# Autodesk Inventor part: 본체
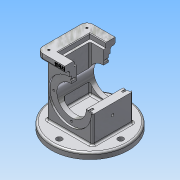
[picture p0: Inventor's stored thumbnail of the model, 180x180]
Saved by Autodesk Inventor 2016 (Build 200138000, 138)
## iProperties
Created: 2018-10
Part Number: 본체
Material: 알루미늄 6061
Document SubType Name: Modeling
Designer: Administrator
Density: 2.7 g/cm^3
Appearance: 알루미늄 - 평지
Mass: 984.575 g
Surface Area: 743.905 cm^2
Volume: 364.657 cm^3
Author: Administrator
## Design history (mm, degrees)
sketch "스케치1"
  geometry: C1 r 62.5 at (0, 0); 1 further point
  constraints: 1 centre point, 1 coincident
  dimensions: "d0" = 125 diameter of C1
extrude "돌출1" new body sketch "스케치1" distance "d1" = 10; taper "d2" = 0 deg
sketch "스케치3"
  geometry: L1 (-37, 33)-(37, 33); L2 (37, 33)-(37, -33); L3 (37, -33)-(-37, -33); L4 (-37, -33)-(-37, 33); L5 (-37, 33)-(37, -33); L6 (37, 33)-(-37, -33); 1 further point
  constraints: 12 end point, 2 midpoint, 2 parallel, 1 horizontal, 1 perpendicular
  dimensions: "d3" = 74 distance of L2.end L3.end; "d4" = 66 distance of L1.end L2.end
extrude "돌출2" join sketch "스케치3" distance "d5" = 108; taper "d6" = 0 deg
sketch "스케치4"
  geometry: L1 (-46, 41)-(46, 41); L2 (46, 41)-(46, -41); L3 (46, -41)-(-46, -41); L4 (-46, -41)-(-46, 41); L5 (-46, 41)-(46, -41); L6 (46, 41)-(-46, -41); 1 further point
  constraints: 12 end point, 2 midpoint, 2 parallel, 1 horizontal, 1 perpendicular
  dimensions: "d7" = 92 distance of L2.end L3.end; "d8" = 82 distance of L1.end L2.end
extrude "돌출3" join sketch "스케치4" distance "d9" = 10; taper "d10" = 0 deg
sketch "스케치5"
  geometry: L1 (0, 0)-(0, 18); L2 (0, 18)-(24.826, 18); L3 (24.826, 18)-(28, 0); L4 (28, 0)-(0, 0); 1 further point
  constraints: 8 end point, 1 coincident, 1 parallel, 1 perpendicular, 1 vertical
  dimensions: "d11" = 18 distance between parallel lines of L4 L2; "d12" = 56 diameter of L3.end L1; "d13" = 80 deg angle of L4 L3
revolve "회전1" sketch "스케치5" stored, may be unused: angle "d14" = 90 deg
sketch "스케치6"
  geometry: L1 (-26, 26)-(26, 26); L2 (26, 26)-(26, -26); L3 (26, -26)-(-26, -26); L4 (-26, -26)-(-26, 26); L5 (-26, 26)-(26, -26); L6 (26, 26)-(-26, -26); 1 further point
  constraints: 12 end point, 2 midpoint, 2 parallel, 1 horizontal, 1 perpendicular
  dimensions: "d15" = 52 distance of L2.end L3.end; "d16" = 52 distance of L1.end L2.end
extrude "돌출4" cut sketch "스케치6" distance "d17" = 8; taper "d18" = 0 deg
sketch "스케치7"
  geometry: L1 (-22, 22)-(22, 22); L2 (22, 22)-(22, -22); L3 (22, -22)-(-22, -22); L4 (-22, -22)-(-22, 22); L5 (-22, 22)-(22, -22); L6 (22, 22)-(-22, -22); 1 further point
  constraints: 12 end point, 2 midpoint, 2 parallel, 1 horizontal, 1 perpendicular
  dimensions: "d19" = 44 distance of L2.end L3.end; "d20" = 44 distance of L1.end L2.end
extrude "돌출5" cut sketch "스케치7" distance "d21" = 74; taper "d22" = 0 deg
sketch "스케치8"
  geometry: 1 further point
sketch "스케치9"
  geometry: C1 r 35 at (37, 44); 1 further point
  constraints: 1 centre point, 1 vertical alignment
  dimensions: "d23" = 70 diameter of C1; "d24" = 54 distance of point (37, -10) C1.centre
extrude "돌출6" cut sketch "스케치9" distance "d25" = 3; taper "d26" = 0 deg
sketch "스케치10" dims "d27" = 58
  geometry: C1 r 35 at (0, 0) reference; 3 further points
  constraints: 2 vertical alignment, 1 coincident, 2 other
hole "구멍1" sketch "스케치10" at (0, 29) diameter "d28" = 3.242; stored, may be unused: countersink angle "d32" = 90 deg, drill point angle "d34" = 118 deg; dims "d29" = 4, "d30" = 4, "d31" = 2, "d33" = 6
sketch "스케치11"
  geometry: C1 r 35 at (0, 0) reference; C2 r 24 at (0, 0); 1 further point
  constraints: 1 centre point, 1 coincident
  dimensions: "d38" = 48 diameter of C2
extrude "돌출7" cut sketch "스케치11" stored distance "d39" = 3; taper "d40" = 0 deg
fillet "모깎기1" dims "d41" = 10
hole "구멍2" diameter "d44" = 3.242; stored, may be unused: countersink angle "d48" = 90 deg, drill point angle "d50" = 118 deg; dims "d42" = 10, "d43" = 10, "d45" = 4, "d46" = 4, "d47" = 2, "d49" = 6
hole "구멍3" diameter "d53" = 3.242; stored, may be unused: countersink angle "d57" = 90 deg, drill point angle "d59" = 118 deg; dims "d51" = 10, "d52" = 10, "d54" = 4, "d55" = 4, "d56" = 2, "d58" = 6
hole "구멍4" diameter "d62" = 3.242; stored, may be unused: countersink angle "d66" = 90 deg, drill point angle "d68" = 118 deg; dims "d60" = 10, "d61" = 10, "d63" = 4, "d64" = 4, "d65" = 2, "d67" = 6
hole "구멍5" diameter "d71" = 3.242; stored, may be unused: countersink angle "d75" = 90 deg, drill point angle "d77" = 118 deg; dims "d69" = 10, "d70" = 10, "d72" = 4, "d73" = 4, "d74" = 2, "d76" = 6
sketch "스케치12"
  geometry: 3 further points
  constraints: 2 horizontal alignment
  dimensions: "d78" = 37 distance of point (10, 33) point (-27, 33); "d79" = 43 distance of point (-70, 33) point (-27, 33)
hole "구멍6" sketch "스케치12" at (-70, 33) diameter "d80" = 4.134; stored, may be unused: countersink angle "d84" = 90 deg, drill point angle "d86" = 118 deg; dims "d81" = 10, "d82" = 4, "d83" = 2, "d85" = 14.2
sketch "스케치13"
  geometry: 2 further points
  constraints: 1 horizontal alignment
  dimensions: "d87" = 37 distance of point (10, 33) point (-27, 33)
hole "구멍7" sketch "스케치13" at (-27, 33) diameter "d88" = 4.134; stored, may be unused: countersink angle "d92" = 90 deg, drill point angle "d94" = 118 deg; dims "d89" = 10, "d90" = 4, "d91" = 2, "d93" = 14.2
sketch "스케치15" dims "d95" = 100
  geometry: 3 further points
  constraints: 2 vertical alignment, 1 coincident, 2 other
hole "구멍8" sketch "스케치15" at (0, 50) diameter "d96" = 9; stored, may be unused: countersink angle "d100" = 90 deg, drill point angle "d102" = 118 deg; dims "d97" = 10, "d98" = 4, "d99" = 2, "d101" = 14.2
sketch "스케치16"
  geometry: L1 (72, 0)-(0, 0) reference; L2 (-10, 0)-(-10, -10) reference; 2 further points
  constraints: 1 other
  dimensions: "d106" = 4 distance from line of point (36, -4) L1; "d107" = 46 distance from line of L2 point (36, -4)
feature "엠보싱1" sketch "스케치16" dims "d0" = 125, "d108" = 0.5, "d109" = 0
chamfer "모따기1" distance "d110" = 1; stored, may be unused: second distance "d111" = 2, angle "d112" = 45 deg
fillet "모깎기2" dims "d113" = 3
fillet "모깎기3" dims "d114" = 3
fillet "모깎기4" dims "d115" = 3
fillet "모깎기5" dims "d116" = 3
fillet "모깎기6" dims "d117" = 3
sketch "스케치17"
  geometry: L1 (0, 54)-(-81.526, 54); L2 (-81.526, 54)-(-81.526, 127.509); L3 (-81.526, 127.509)-(0, 127.509); L4 (0, 127.509)-(0, 54); C1 r 24 at (0, 54) reference; 1 further point
  constraints: 8 end point, 2 parallel, 1 horizontal, 1 perpendicular
extrude "돌출8" cut sketch "스케치17" stored distance "d118" = 0; taper "d119" = 0 deg
node "솔리드1"
pattern_circular "원형 패턴1" dims angle "d36" = 360 deg
mirror "대칭1"
pattern_circular "원형 패턴2" dims angle "d104" = 360 deg
